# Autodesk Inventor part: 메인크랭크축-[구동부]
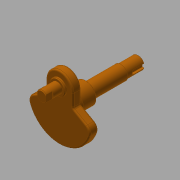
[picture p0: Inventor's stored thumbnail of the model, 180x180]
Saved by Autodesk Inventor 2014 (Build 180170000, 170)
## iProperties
Created: 2016-11
Part Number: 메인크랭크축-[구동부]
Material: 강철, 탄소
Document SubType Name: Modeling
Designer: mduedu
Density: 7.87 g/cm^3
Mass: 807.42 g
Surface Area: 206.102 cm^2
Volume: 102.595 cm^3
Appearance: 주황색
Author: mduedu
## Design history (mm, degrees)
sketch "스케치1" dims "d8" = 65
  geometry: L1 (-19, 26.368)-(-19, 8.368); L2 (-19, 8.368)-(-44.545, -6.381); L3 (0, 26.368)-(0, -45); L4 (19, 26.368)-(19, 8.368); L5 (19, 8.368)-(44.545, -6.381); C1 r 10 at (0, 0); C2 r 17.5 at (0, 0); A1 r 45 centre (0, 0) between (-44.545, -6.381) and (0, -45); A2 r 19 centre (0, 26.368) between (0, 45.368) and (-19, 26.368); A3 r 19 centre (0, 26.368) between (19, 26.368) and (0, 45.368); A4 r 45 centre (0, 0) between (0, -45) and (44.545, -6.381); 2 further points
  constraints: 10 end point, 8 point on circle, 6 centre point, 4 coincident, 3 symmetric about line, 2 point on line, 1 parallel, 1 tangent, 1 vertical, 1 vertical alignment, 5 other
  dimensions: "d1" = 20 diameter of C1; "d2" = 35 diameter of C2; "d4" = 18 distance of L1.start L1.end; "d5" = 120 deg angle of L2 L1; "d6" = 45 radius of A1; "d9" = 19 radius of A2
extrude "돌출1" new body sketch "스케치1" distance "d10" = 12; taper "d11" = 0 deg
extrude "돌출2" join sketch "스케치1" distance "d12" = 5; taper "d13" = 0 deg
extrude "돌출3" join sketch "스케치1" distance "d14" = 100; taper "d15" = 0 deg
sketch "스케치2"
  geometry: C1 r 7.5 at (0, 26.368); C2 r 11 at (0, 26.368); A1 r 19 centre (0, 26.368) between (19, 26.368) and (-19, 26.368) reference; 1 further point
  constraints: 2 centre point, 2 coincident
  dimensions: "d16" = 15 diameter of C1; "d17" = 22 diameter of C2
extrude "돌출4" join sketch "스케치2" distance "d18" = 3; taper "d19" = 0 deg
extrude "돌출5" join sketch "스케치2" distance "d20" = 25; taper "d21" = 0 deg
node "작업 평면1"
sketch "스케치3"
  geometry: L1 (-5.75, -4.815)-(5.75, -4.815); L2 (5.75, -4.815)-(5.75, 4.815); L3 (5.75, 4.815)-(-5.75, 4.815); L4 (-5.75, 4.815)-(-5.75, -4.815); L5 (-5.75, -4.815)-(5.75, 4.815); L6 (5.75, -4.815)-(-5.75, 4.815); A1 r 7.5 centre (0, 0) between (-5.75, 4.815) and (-5.75, -4.815); A2 r 7.5 centre (0, 0) between (5.75, -4.815) and (5.75, 4.815); 2 further points
  constraints: 12 end point, 4 point on circle, 2 centre point, 2 midpoint, 2 parallel, 1 coincident, 1 horizontal, 1 perpendicular, 2 other
  dimensions: "d23" = 11.5 distance between parallel lines of L2 L4
extrude "돌출6" cut sketch "스케치3" stored distance "d25" = 25; taper "d26" = 0 deg
fillet "모깎기1" dims "d27" = 3, "d29" = 10
fillet "모깎기2" dims "d28" = 2
sketch "스케치4"
  geometry: C1 r 15 at (0, 0); 1 further point
  constraints: 1 centre point, 1 coincident
  dimensions: "d30" = 30 diameter of C1
extrude "돌출7" join sketch "스케치4" distance "d31" = 21; taper "d32" = 0 deg
sketch "스케치5"
  geometry: C1 r 10 at (0, 0) reference; C2 r 9 at (0, 0); 1 further point
  constraints: 1 centre point
  dimensions: "d33" = 1 radial gap between concentric circles of C1 C2
extrude "돌출8" cut sketch "스케치5" distance "d34" = 25; taper "d35" = 0 deg
node "작업 평면2"
sketch "스케치6"
  geometry: L1 (-9, 0)-(9, 0) reference; L2 (-3, 0)-(3, 0); L3 (3, 0)-(3, 15); L4 (-3, 15)-(-3, 0); A1 r 3 centre (0, 15) between (3, 15) and (-3, 15); 1 further point
  constraints: 6 end point, 2 point on circle, 2 tangent, 1 centre point, 1 horizontal, 1 parallel, 1 perpendicular, 1 point on line, 1 vertical alignment
  dimensions: "d36" = 18 dimension on A1 L1; "d37" = 6 distance between parallel lines of L3 L4
extrude "돌출9" cut sketch "스케치6" distance "d38" = 3.5; taper "d39" = 0 deg
chamfer "모따기1" distance "d40" = 1; stored, may be unused: second distance "d41" = 2, angle "d42" = 45 deg
chamfer "모따기2" distance "d43" = 1; stored, may be unused: second distance "d44" = 2, angle "d45" = 45 deg
node "솔리드1"
node "투영된 루프1"
other parameters: "d3" = 38, "d22" = 13
